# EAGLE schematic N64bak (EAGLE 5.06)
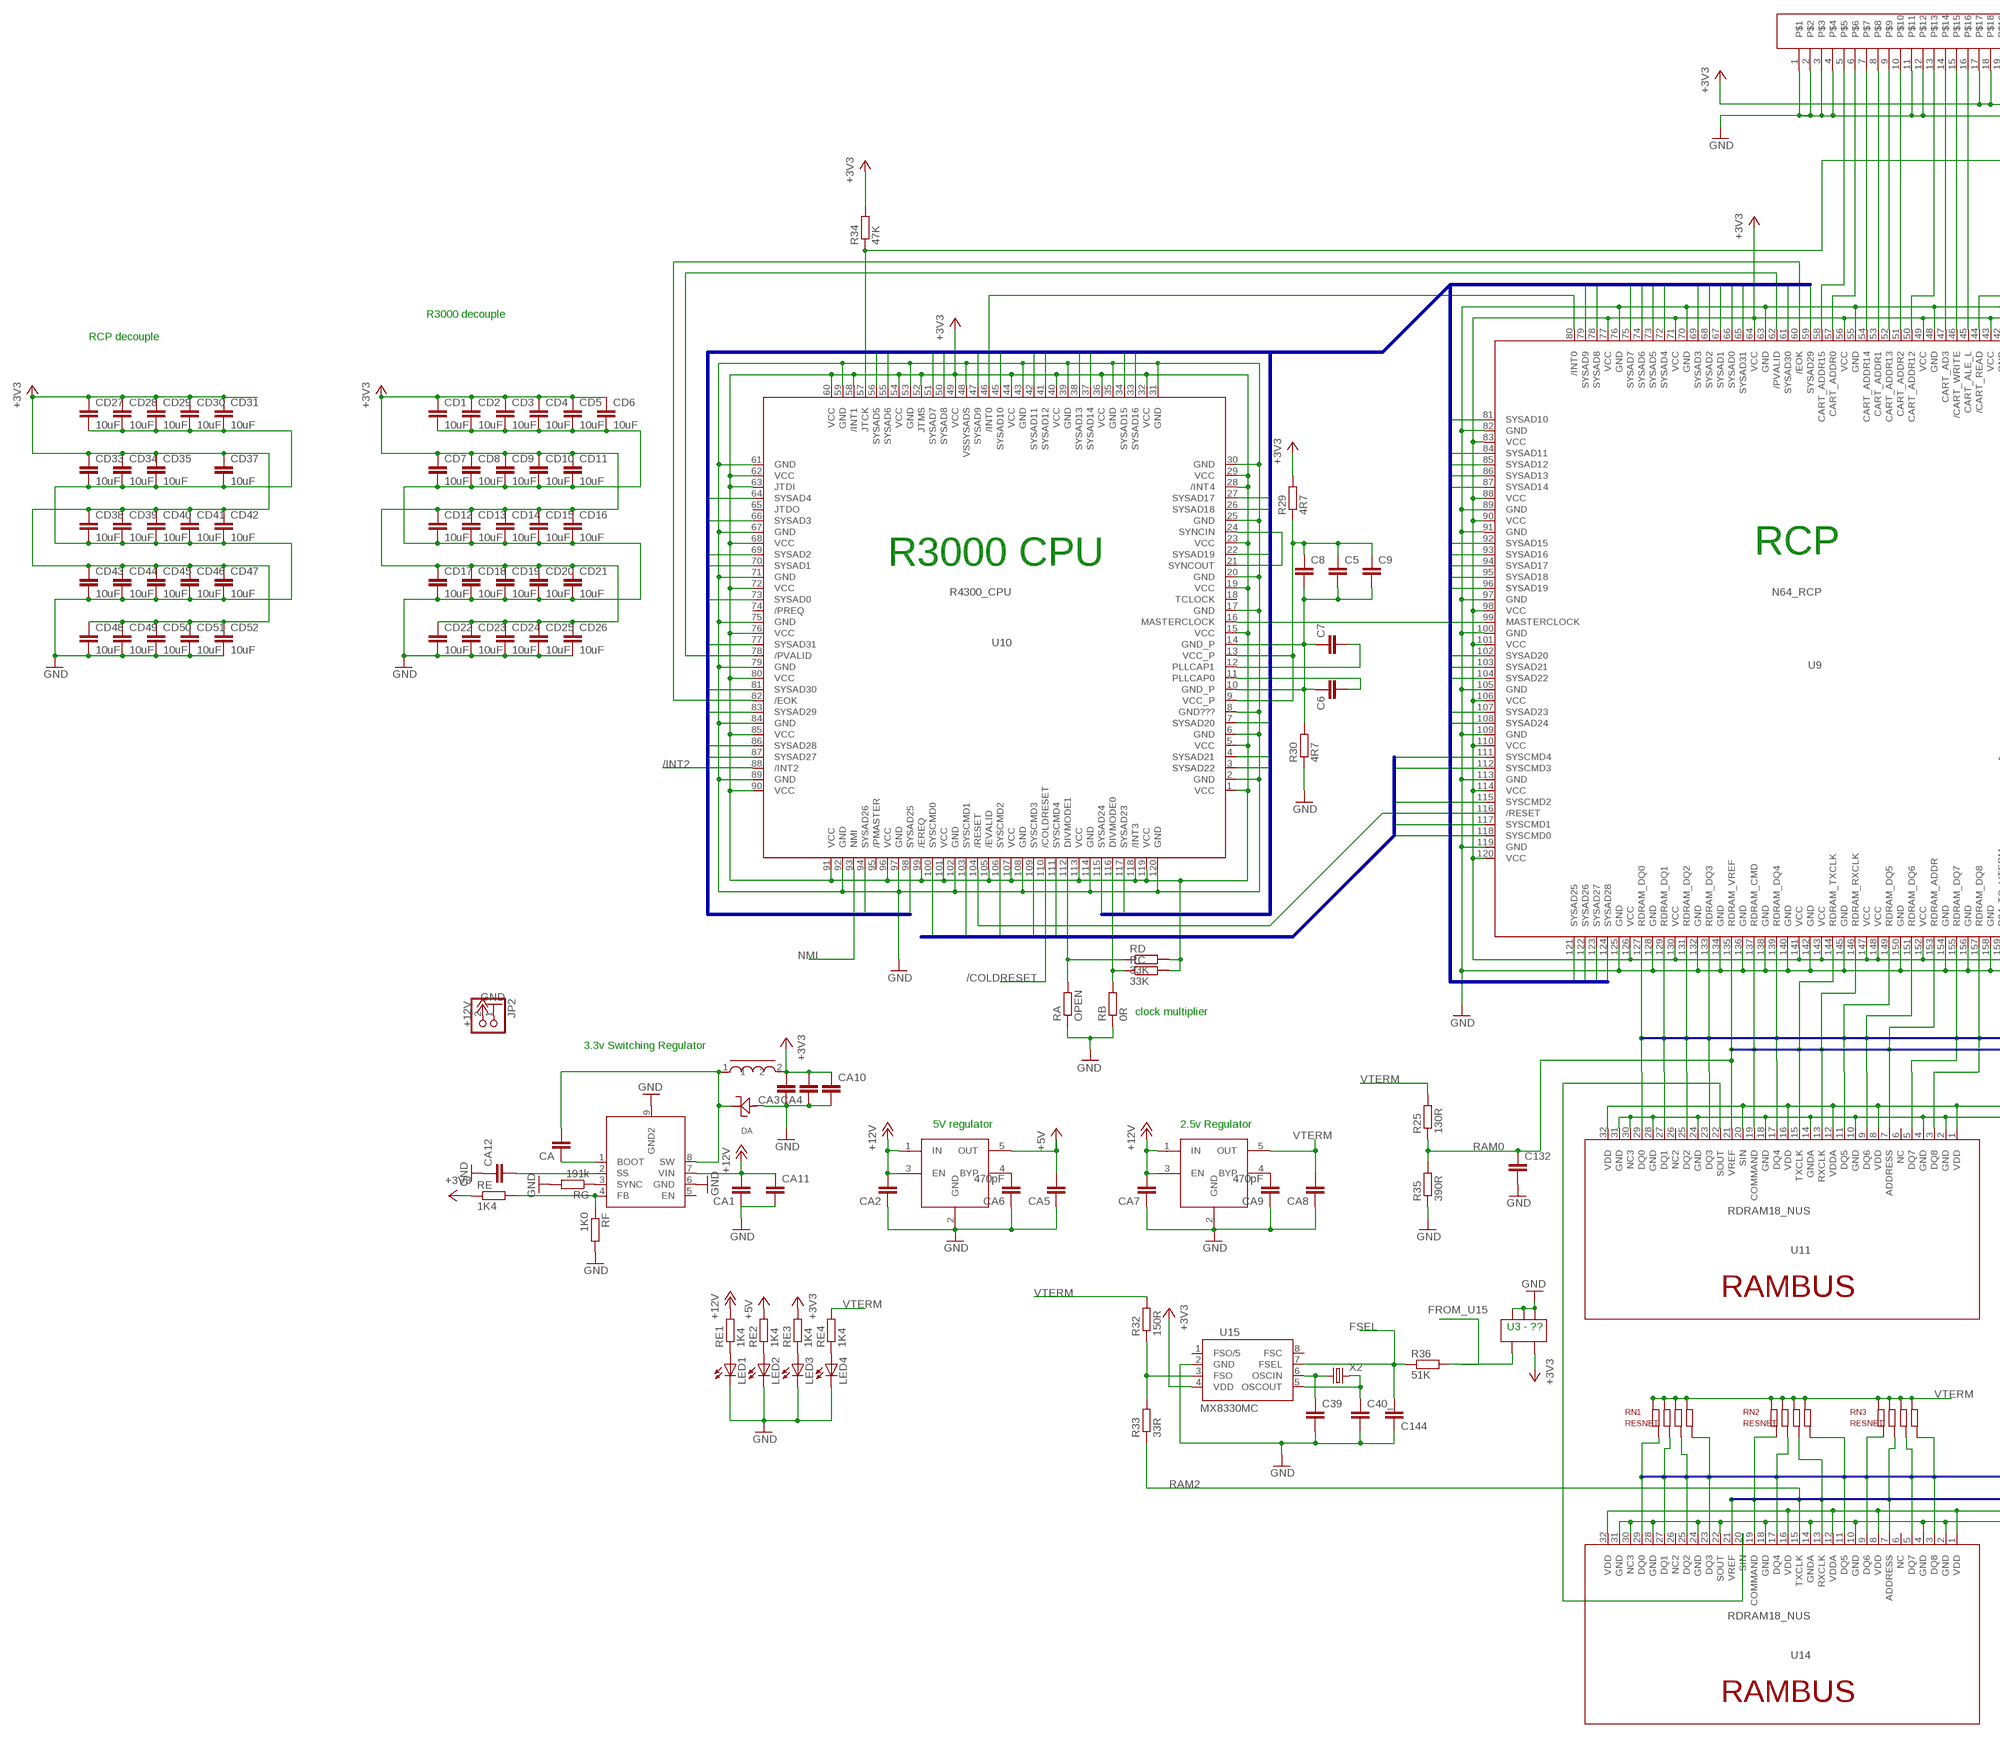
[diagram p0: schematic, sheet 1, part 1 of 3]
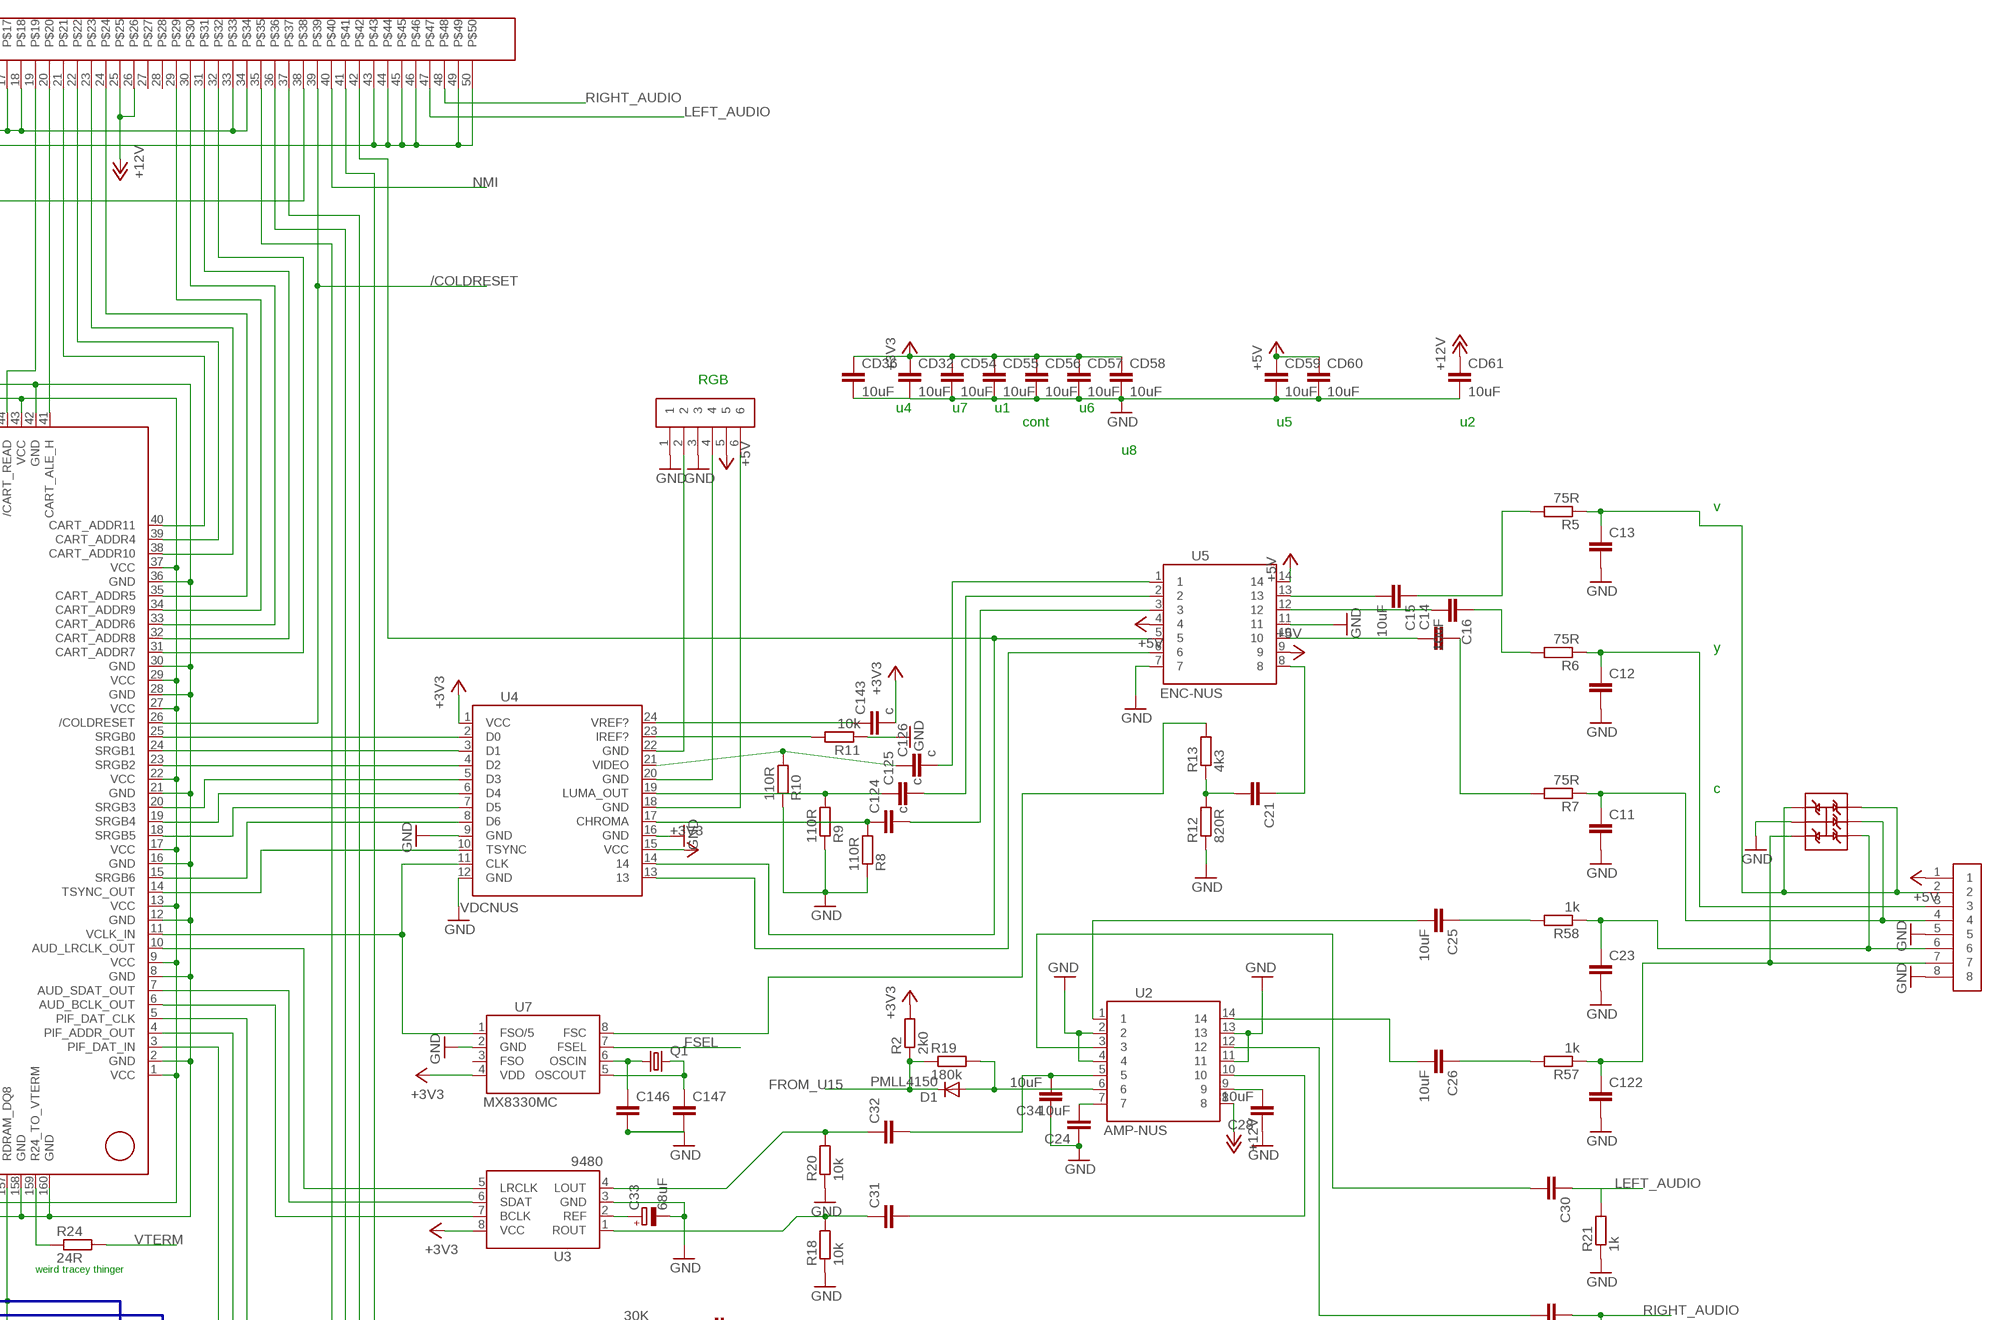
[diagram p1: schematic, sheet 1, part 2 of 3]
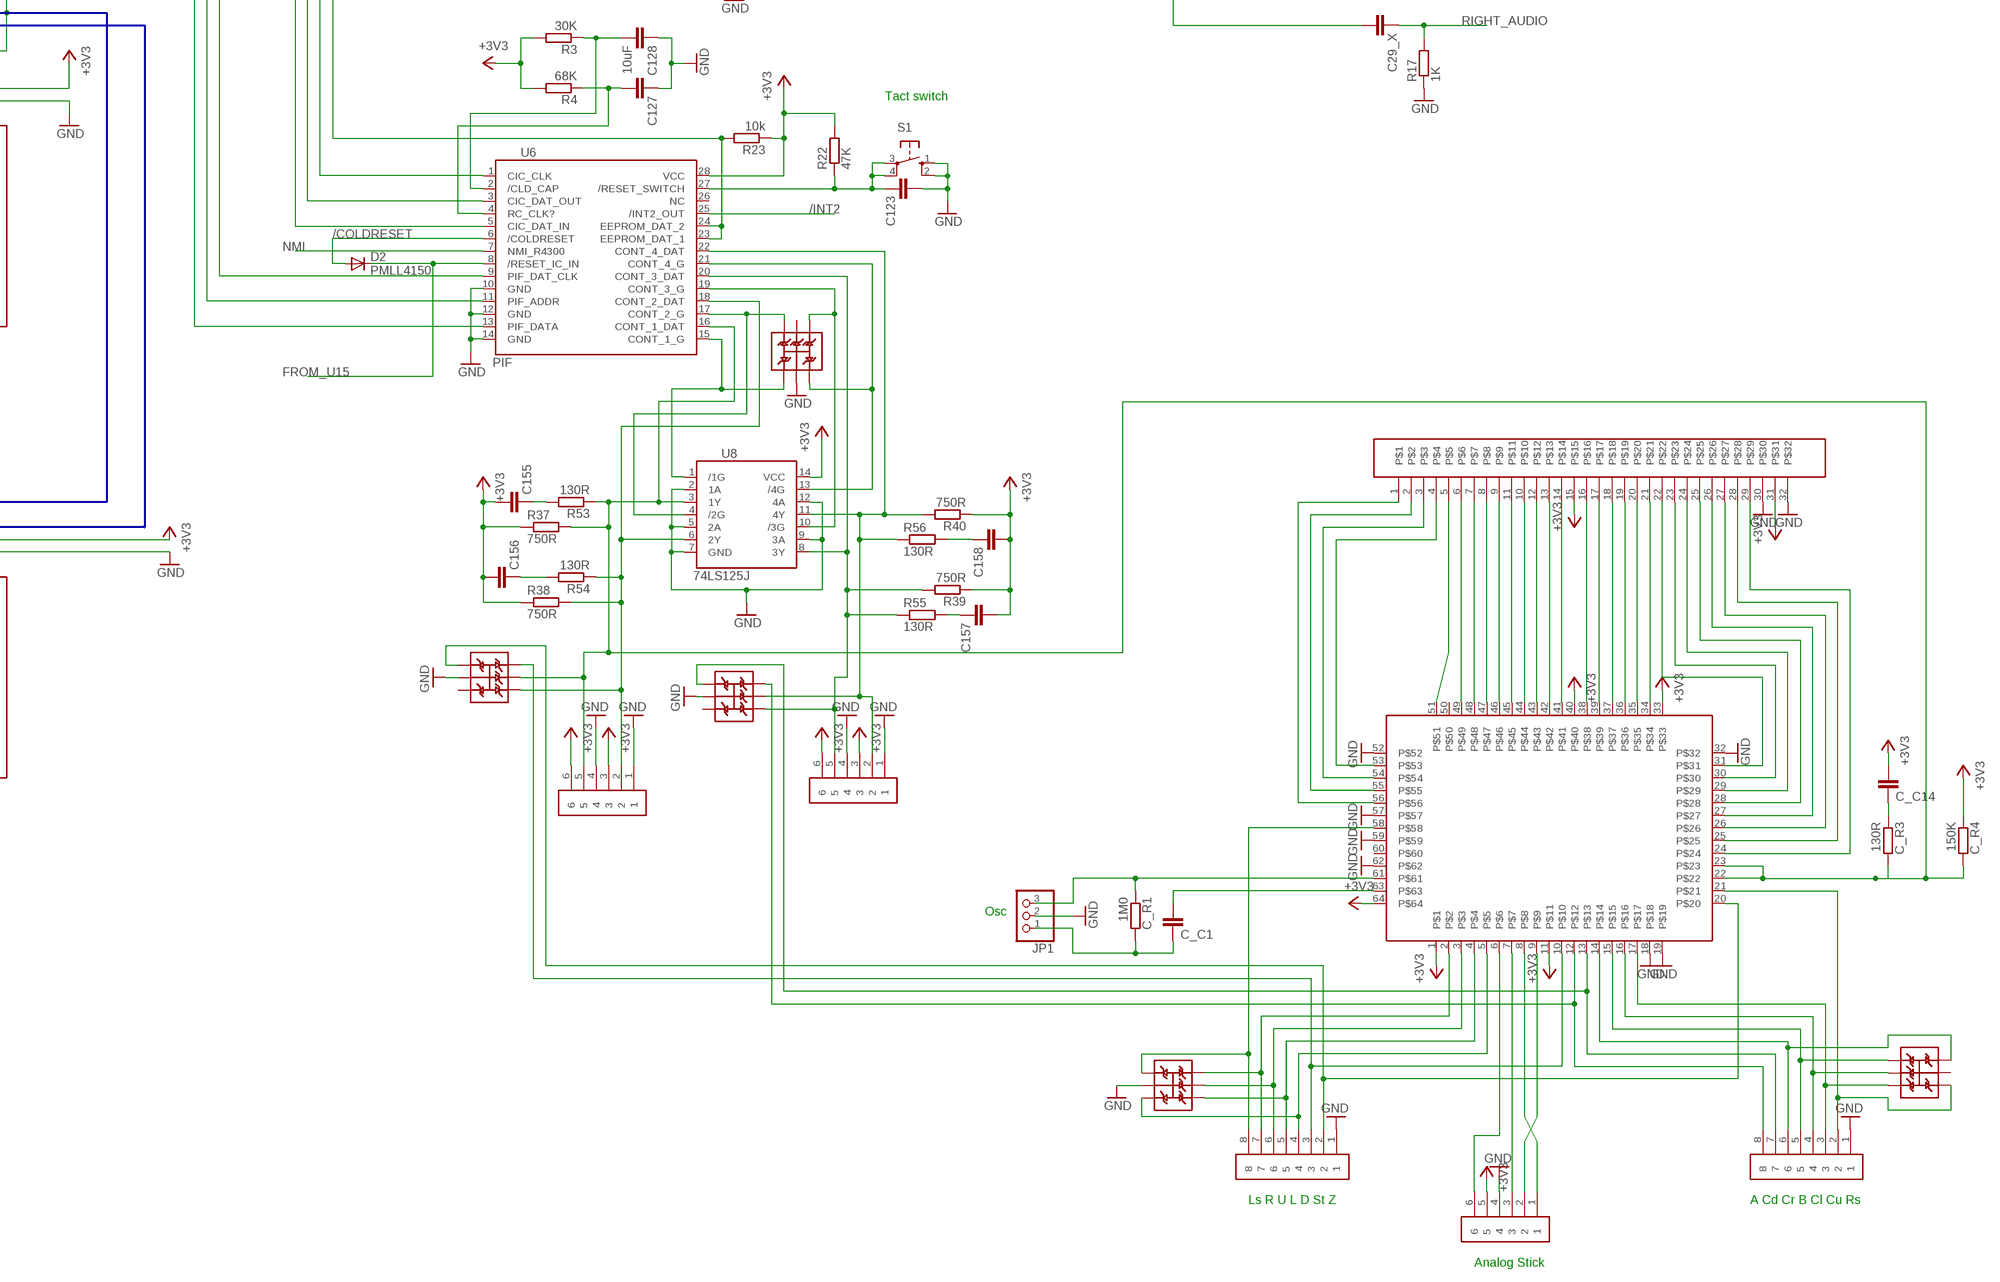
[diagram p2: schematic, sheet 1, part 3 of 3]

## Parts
3V3  LM22680  [PSOP-8]
AV  PINHEAD-1X8  [2MMPINHEAD-1X8]
BUTT1  PINHEAD-1X8  [2MMPINHEAD-1X8]
BUTT2  PINHEAD-1X8  [2MMPINHEAD-1X8]
C5  C-EUC0805K  [C0805K]
C6  C-EUC0805  [C0805]
C7  C-EUC0805  [C0805]
C8  C-EUC0805  [C0805]
C9  C-EUC0805  [C0805]
C11  C-EUC0805  [C0805]
C12  C-EUC0805  [C0805]
C13  C-EUC0805  [C0805]
C14  C-EUC0805  [C0805]
C15  10uF  C-EUC0805  [C0805]
C16  10uF  C-EUC0805  [C0805]
C21  C-EUC0805  [C0805]
C23  C-EUC0805  [C0805]
C24  10uF  C-EUC0805  [C0805]
C25  10uF  C-EUC0805  [C0805]
C26  10uF  C-EUC0805  [C0805]
C28  10uF  C-EUC0805  [C0805]
C29_X  C-EUC0805  [C0805]
C30  C-EUC0805  [C0805]
C31  C-EUC0805  [C0805]
C32  C-EUC0805  [C0805]
C33  68uF  CPOL-EUC/6032-28R  [C/6032-28R]
C34  10uF  C-EUC0805  [C0805]
C39  C-EUC0805  [C0805]
C40_  C-EUC0805  [C0805]
C122  C-EUC0805  [C0805]
C123  C-EUC0805  [C0805]
C124  c  C-EUC0805  [C0805]
C125  c  C-EUC0805  [C0805]
C126  c  C-EUC0805  [C0805]
C127  C-EUC0805  [C0805]
C128  10uF  C-EUC0805  [C0805]
C132  C-EUC0805  [C0805]
C143  c  C-EUC0805  [C0805]
C144  C-EUC0805  [C0805]
C146  C-EUC0805  [C0805]
C147  C-EUC0805  [C0805]
C155  C-EUC0805  [C0805]
C156  C-EUC0805  [C0805]
C157  C-EUC0805  [C0805]
C158  C-EUC0805  [C0805]
C_C1  C-EUC0805  [C0805]
C_C14  C-EUC0805  [C0805]
C_R1  1M0  R-EU_M0805  [M0805]
C_R3  130R  R-EU_M0805  [M0805]
C_R4  150K  R-EU_M0805  [M0805]
C_U1  CNT-NUS  [PQFP64]
CA  C-EUC1206K  [C1206K]
CA1  C-EUC1206K  [C1206K]
CA2  C-EUC0805K  [C0805K]
CA3  C-EUC1210K  [C1210K]
CA4  C-EUC1206K  [C1206K]
CA5  C-EUC0805K  [C0805K]
CA6  470pF  C-EUC0805K  [C0805K]
CA7  C-EUC0805K  [C0805K]
CA8  C-EUC0805K  [C0805K]
CA9  470pF  C-EUC0805K  [C0805K]
CA10  C-EUC0805K  [C0805K]
CA11  C-EUC0805K  [C0805K]
CA12  C-EUC0805K  [C0805K]
CD1  10uF  C-EUC0805  [C0805]
CD2  10uF  C-EUC0805  [C0805]
CD3  10uF  C-EUC0805  [C0805]
CD4  10uF  C-EUC0805  [C0805]
CD5  10uF  C-EUC0805  [C0805]
CD6  10uF  C-EUC0805  [C0805]
CD7  10uF  C-EUC0805  [C0805]
CD8  10uF  C-EUC0805  [C0805]
CD9  10uF  C-EUC0805  [C0805]
CD10  10uF  C-EUC0805  [C0805]
CD11  10uF  C-EUC0805  [C0805]
CD12  10uF  C-EUC0805  [C0805]
CD13  10uF  C-EUC0805  [C0805]
CD14  10uF  C-EUC0805  [C0805]
CD15  10uF  C-EUC0805  [C0805]
CD16  10uF  C-EUC0805  [C0805]
CD17  10uF  C-EUC0805  [C0805]
CD18  10uF  C-EUC0805  [C0805]
CD19  10uF  C-EUC0805  [C0805]
CD20  10uF  C-EUC0805  [C0805]
CD21  10uF  C-EUC0805  [C0805]
CD22  10uF  C-EUC0805  [C0805]
CD23  10uF  C-EUC0805  [C0805]
CD24  10uF  C-EUC0805  [C0805]
CD25  10uF  C-EUC0805  [C0805]
CD26  10uF  C-EUC0805  [C0805]
CD27  10uF  C-EUC0805  [C0805]
CD28  10uF  C-EUC0805  [C0805]
CD29  10uF  C-EUC0805  [C0805]
CD30  10uF  C-EUC0805  [C0805]
CD31  10uF  C-EUC0805  [C0805]
CD32  10uF  C-EUC0805  [C0805]
CD33  10uF  C-EUC0805  [C0805]
CD34  10uF  C-EUC0805  [C0805]
CD35  10uF  C-EUC0805  [C0805]
CD36  10uF  C-EUC0805  [C0805]
CD37  10uF  C-EUC0805  [C0805]
CD38  10uF  C-EUC0805  [C0805]
CD39  10uF  C-EUC0805  [C0805]
CD40  10uF  C-EUC0805  [C0805]
CD41  10uF  C-EUC0805  [C0805]
CD42  10uF  C-EUC0805  [C0805]
CD43  10uF  C-EUC0805  [C0805]
CD44  10uF  C-EUC0805  [C0805]
CD45  10uF  C-EUC0805  [C0805]
CD46  10uF  C-EUC0805  [C0805]
CD47  10uF  C-EUC0805  [C0805]
CD48  10uF  C-EUC0805  [C0805]
CD49  10uF  C-EUC0805  [C0805]
CD50  10uF  C-EUC0805  [C0805]
CD51  10uF  C-EUC0805  [C0805]
CD52  10uF  C-EUC0805  [C0805]
CD54  10uF  C-EUC0805  [C0805]
CD55  10uF  C-EUC0805  [C0805]
CD56  10uF  C-EUC0805  [C0805]
CD57  10uF  C-EUC0805  [C0805]
CD58  10uF  C-EUC0805  [C0805]
CD59  10uF  C-EUC0805  [C0805]
CD60  10uF  C-EUC0805  [C0805]
CD61  10uF  C-EUC0805  [C0805]
CONT1  PINHEAD-1X6  [2MMPINHEAD-1X6]
CONT2  PINHEAD-1X6  [2MMPINHEAD-1X6]
D1  PMLL4150  [SOD80C]
D2  PMLL4150  [SOD80C]
DA  STKYDIODE  [STKYDIODE]
JOY  PINHEAD-1X6  [2MMPINHEAD-1X6]
JP1  PINHD-1X3  [1X03]
JP2  PINHD-1X2  [1X02]
LED1  LEDCHIPLED_0805  [CHIPLED_0805]
LED2  LEDCHIPLED_0805  [CHIPLED_0805]
LED3  LEDCHIPLED_0805  [CHIPLED_0805]
LED4  LEDCHIPLED_0805  [CHIPLED_0805]
Q1  CRYTALHC49S  [HC49/S]
R2  2k0  R-EU_M0805  [M0805]
R3  30K  R-EU_M0805  [M0805]
R4  68K  R-EU_M0805  [M0805]
R5  75R  R-EU_M0805  [M0805]
R6  75R  R-EU_M0805  [M0805]
R7  75R  R-EU_M0805  [M0805]
R8  110R  R-EU_M0805  [M0805]
R9  110R  R-EU_M0805  [M0805]
R10  110R  R-EU_M0805  [M0805]
R11  10k  R-EU_M0805  [M0805]
R12  820R  R-EU_M0805  [M0805]
R13  4k3  R-EU_M0805  [M0805]
R17  1K  R-EU_M0805  [M0805]
R18  10k  R-EU_M0805  [M0805]
R19  180k  R-EU_M0805  [M0805]
R20  10k  R-EU_M0805  [M0805]
R21  1k  R-EU_M0805  [M0805]
R22  47K  R-EU_M0805  [M0805]
R23  10k  R-EU_M0805  [M0805]
R24  24R  R-EU_M0805  [M0805]
R25  130R  R-EU_M0805  [M0805]
R29  4R7  R-EU_M0805  [M0805]
R30  4R7  R-EU_M0805  [M0805]
R32  150R  R-EU_M0805  [M0805]
R33  33R  R-EU_M0805  [M0805]
R34  47K  R-EU_M0805  [M0805]
R35  390R  R-EU_M0805  [M0805]
R36  51K  R-EU_M0805  [M0805]
R37  750R  R-EU_M0805  [M0805]
R38  750R  R-EU_M0805  [M0805]
R39  750R  R-EU_M0805  [M0805]
R40  750R  R-EU_M0805  [M0805]
R53  130R  R-EU_M0805  [M0805]
R54  130R  R-EU_M0805  [M0805]
R55  130R  R-EU_M0805  [M0805]
R56  130R  R-EU_M0805  [M0805]
R57  1k  R-EU_M0805  [M0805]
R58  1k  R-EU_M0805  [M0805]
RA  OPEN  R-EU_M0805  [M0805]
RB  0R  R-EU_M0805  [M0805]
RC  33K  R-EU_M0805  [M0805]
RD  33K  R-EU_M0805  [M0805]
RE  1K4  R-EU_M0805  [M0805]
RE1  1K4  R-EU_M0805  [M0805]
RE2  1K4  R-EU_M0805  [M0805]
RE3  1K4  R-EU_M0805  [M0805]
RE4  1K4  R-EU_M0805  [M0805]
RF  1K0  R-EU_M0805  [M0805]
RG  191k  R-EU_M0805  [M0805]
RGB  PINHEAD-1X6  [2MMPINHEAD-1X6]
RN1  RESNET  [RESARRAY]
RN2  RESNET  [RESARRAY]
RN3  RESNET  [RESARRAY]
S1  10-XX  [B3F-10XX]
TVS1  TVS  [SC-74]
TVS2  TVS  [SC-74]
TVS3  TVS  [SC-74]
TVS4  TVS  [SC-74]
TVS5  TVS  [SC-74]
TVS6  TVS  [SC-74]
U2  AMP-NUS  [SO14]
U3  9480  [SO8]
U3_  U3  [SOT23-5]
U4  VDCNUS  [SO24]
U5  ENC-NUS  [SO14]
U6  PIF  [SO28W]
U7  MX8330MC  [SO08]
U8  74LS125J  [QSOP14]
U9  N64_RCP  [PQFP160]
U10  R4300_CPU  [QFP120]
U11  RDRAM18_NUS  [SHP32]
U12  MIC5219  [SOT23-5]
U13  MIC5219  [SOT23-5]
U14  RDRAM18_NUS  [SHP32]
U15  MX8330MC  [SO08]
U$37  PINHEAD-25X2  [PINHEAD-25X2]
U$38  PINHEAD-16X2SMALLER  [2MMPINHEAD-16X2]
U$52  INDUCTOR  [INDUCTOR]
X2  CRYTALHC49S  [HC49/S]

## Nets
3V3: C143.2 R2.2 R34.2 RE3.2 RE.1 ; supply symbol labelled +3V3
+3V3: C155.2 C156.2 C157.2 C158.2 C_C14.2 C_R4.1 C_U1.1 C_U1.11 C_U1.33 C_U1.40 C_U1.64 CA3.2 CA4.2 CA10.1 CD1.1 CD2.1 CD3.1 CD4.1 CD5.1 CD6.1 CD7.1 CD8.1 CD9.1 CD10.1 CD11.1 CD12.1 CD13.1 CD14.1 CD15.1 CD16.1 CD17.1 CD18.1 CD19.1 CD20.1 CD21.1 CD22.1 CD23.1 CD24.1 CD25.1 CD26.1 CD27.1 CD28.1 CD29.1 CD30.1 CD31.1 CD32.1 CD33.1 CD34.1 CD35.1 CD36.1 CD37.1 CD38.1 CD39.1 CD40.1 CD41.1 CD42.1 CD43.1 CD44.1 CD45.1 CD46.1 CD47.1 CD48.1 CD49.1 CD50.1 CD51.1 CD52.1 CD54.1 CD55.1 CD56.1 CD57.1 CD58.1 CONT1.3 CONT1.6 CONT2.3 CONT2.6 JOY.5 R3.2 R4.2 R22.2 R23.1 R29.2 R37.1 R38.1 R39.1 R40.1 RC.2 RD.2 U3.8(VCC) U3_.5 U4.1(VCC) U4.15(VCC) U6.28(VCC) U7.4(VDD) U8.14(VCC) U9.1(VCC) U9.9(VCC) U9.13(VCC) U9.17(VCC) U9.22(VCC) U9.27(VCC) U9.29(VCC) U9.37(VCC) U9.43(VCC) U9.49(VCC) U9.56(VCC) U9.64(VCC) U9.71(VCC) U9.77(VCC) U9.83(VCC) U9.88(VCC) U9.90(VCC) U9.98(VCC) U9.101(VCC) U9.106(VCC) U9.110(VCC) U9.114(VCC) U9.120(VCC) U9.126(VCC) U9.130(VCC) U9.141(VCC) U9.143(VCC) U9.147(VCC) U9.148(VCC) U9.152(VCC) U10.1(VCC) U10.5(VCC) U10.15(VCC) U10.19(VCC) U10.23(VCC) U10.28(/INT4) U10.29(VCC) U10.32(VCC) U10.36(VCC) U10.40(VCC) U10.44(VCC) U10.49(VCC) U10.52(JTMS) U10.54(VCC) U10.58(/INT1) U10.60(VCC) U10.62(VCC) U10.63(JTDI) U10.68(VCC) U10.72(VCC) U10.76(VCC) U10.80(VCC) U10.85(VCC) U10.90(VCC) U10.91(VCC) U10.96(VCC) U10.99(/EREQ) U10.101(VCC) U10.105(/EVALID) U10.107(VCC) U10.113(VCC) U10.118(/INT3) U10.119(VCC) U11.1(VDD) U11.8(VDD) U11.12(VDDA) U11.16(VDD) U11.20(SIN) U11.32(VDD) U14.1(VDD) U14.8(VDD) U14.12(VDDA) U14.16(VDD) U14.32(VDD) U15.4(VDD) U$37.17 U$37.18 U$37.33 U$37.34 U$38.15 U$38.31 U$52.2
+5V: AV.1 CA5.2 CD59.1 CD60.1 RE2.2 RGB.5 U5.4 U5.9 U5.14 U13.5(OUT)
+12V: 3V3.7(VIN) CA1.2 CA2.2 CA7.2 CA11.1 CD61.1 JP2.2 RE1.2 U2.8 U12.1(IN) U12.3(EN) U13.1(IN) U13.3(EN) U$37.25 U$37.26
/COLDRESET: D2.A U6.6(/COLDRESET) U9.26(/COLDRESET) U10.110(/COLDRESET) U$37.39
/INT2: U6.25(/INT2_OUT) U10.88(/INT2)
ADJ: 3V3.4(FB) RE.2 RF.1
C16X: C16.1 R6.2
C_C11: C_C1.1 C_R1.2 JP1.1
DQ0: RN1.1 U9.127(RDRAM_DQ0) U11.29(DQ0) U14.29(DQ0)
DQ1: RN1.2 U9.129(RDRAM_DQ1) U11.27(DQ1) U14.27(DQ1)
DQ2: RN1.3 U9.131(RDRAM_DQ2) U11.25(DQ2) U14.25(DQ2)
DQ3: RN1.4 U9.133(RDRAM_DQ3) U11.23(DQ3) U14.23(DQ3)
DQ4: RN2.2 U9.139(RDRAM_DQ4) U11.17(DQ4) U14.17(DQ4)
DQ5: RN2.4 U9.149(RDRAM_DQ5) U11.11(DQ5) U14.11(DQ5)
DQ6: RN3.1 U9.151(RDRAM_DQ6) U11.9(DQ6) U14.9(DQ6)
DQ7: RN3.3 U9.155(RDRAM_DQ7) U11.5(DQ7) U14.5(DQ7)
DQ8: RN3.4 U9.157(RDRAM_DQ8) U11.3(DQ8) U14.3(DQ8)
FROM_U15: D1.C D2.C R2.1 R19.1 R36.2 U3_.4 U6.8(/RESET_IC_IN)
FSEL: C144.2 R36.1 U7.7(FSEL) U15.7(FSEL)
FSO1: R32.1 R33.2 U15.3(FSO)
GND: 3V3.6(GND) 3V3.9(GND2) AV.5 AV.8 BUTT1.1 BUTT2.1 C11.2 C12.2 C13.2 C23.2 C24.1 C28.1 C33.- C34.1 C39.2 C40_.2 C122.2 C123.2 C127.1 C128.1 C132.2 C144.1 C146.2 C147.2 C_U1.18 C_U1.19 C_U1.32 C_U1.52 C_U1.57 C_U1.59 C_U1.62 CA1.1 CA2.1 CA3.1 CA4.1 CA5.1 CA6.1 CA7.1 CA8.1 CA9.1 CA10.2 CA11.2 CA12.1 CD1.2 CD2.2 CD3.2 CD4.2 CD5.2 CD6.2 CD7.2 CD8.2 CD9.2 CD10.2 CD11.2 CD12.2 CD13.2 CD14.2 CD15.2 CD16.2 CD17.2 CD18.2 CD19.2 CD20.2 CD21.2 CD22.2 CD23.2 CD24.2 CD25.2 CD26.2 CD27.2 CD28.2 CD29.2 CD30.2 CD31.2 CD32.2 CD33.2 CD34.2 CD35.2 CD36.2 CD37.2 CD38.2 CD39.2 CD40.2 CD41.2 CD42.2 CD43.2 CD44.2 CD45.2 CD46.2 CD47.2 CD48.2 CD49.2 CD50.2 CD51.2 CD52.2 CD54.2 CD55.2 CD56.2 CD57.2 CD58.2 CD59.2 CD60.2 CD61.2 CONT1.1 CONT1.4 CONT2.1 CONT2.4 DA.+ JOY.4 JP1.2 JP2.1 LED1.C LED2.C LED3.C LED4.C R8.1 R9.1 R10.1 R11.1 R12.1 R17.1 R18.1 R20.1 R21.1 R30.1 R35.1 RA.1 RB.1 RF.2 RG.2 RGB.1 RGB.3 S1.1(S) S1.2(S1) TVS1.2 TVS2.2 TVS3.2 TVS4.2 TVS5.2 U2.2 U2.4 U2.11 U2.13 U3.3(GND) U3_.1 U3_.2 U3_.3 U4.9(GND) U4.12(GND) U4.16(GND) U5.7 U5.11 U6.10(GND) U6.12(GND) U6.14(GND) U7.2(GND) U8.2(1A) U8.5(2A) U8.7(GND) U8.9(3A) U8.12(4A) U9.2(GND) U9.8(GND) U9.12(GND) U9.16(GND) U9.21(GND) U9.28(GND) U9.30(GND) U9.36(GND) U9.42(GND) U9.48(GND) U9.55(GND) U9.63(GND) U9.70(GND) U9.76(GND) U9.82(GND) U9.89(GND) U9.91(GND) U9.97(GND) U9.100(GND) U9.105(GND) U9.109(GND) U9.113(GND) U9.119(GND) U9.125(GND) U9.128(GND) U9.132(GND) U9.134(GND) U9.136(GND) U9.138(GND) U9.140(GND) U9.142(GND) U9.145(GND) U9.150(GND) U9.154(GND) U9.156(GND) U9.158(GND) U9.160(GND) U10.2(GND) U10.6(GND) U10.8(GND???) U10.17(GND) U10.20(GND) U10.25(GND) U10.30(GND) U10.31(GND) U10.35(GND) U10.39(GND) U10.43(GND) U10.48(VSSYSADS) U10.53(GND) U10.59(GND) U10.61(GND) U10.67(GND) U10.71(GND) U10.75(GND) U10.79(GND) U10.84(GND) U10.89(GND) U10.92(GND) U10.97(GND) U10.102(GND) U10.108(GND) U10.114(GND) U10.120(GND) U11.2(GND) U11.4(GND) U11.10(GND) U11.14(GNDA) U11.18(GND) U11.24(GND) U11.28(GND) U11.30(NC3) U11.31(GND) U12.2(GND) U13.2(GND) U14.2(GND) U14.4(GND) U14.10(GND) U14.14(GNDA) U14.18(GND) U14.22(SOUT) U14.24(GND) U14.28(GND) U14.30(NC3) U14.31(GND) U15.2(GND) U$37.1 U$37.2 U$37.3 U$37.4 U$37.11 U$37.12 U$37.43 U$37.44 U$37.45 U$37.46 U$37.49 U$37.50 U$38.30 U$38.32
INT0: U9.80(/INT0) U10.46(/INT0)
LEFT_AUDIO: C30.1 R21.2 U$37.47
N$1: C156.1 R54.2
N$2: C155.1 R53.2
N$3: U4.11(CLK) U7.1(FSO/5) U9.11(VCLK_IN)
N$4: R24.1 U9.159(R24_TO_VTERM)
N$5: C147.1 Q1.2 U7.5(OSCOUT)
N$6: C146.1 Q1.1 U7.6(OSCIN)
N$7: BUTT1.2 C_U1.20 TVS3.1
N$8: RGB.2 U4.22(GND)
N$9: RGB.4 U4.20(GND)
N$10: U6.9(PIF_DAT_CLK) U9.5(PIF_DAT_CLK)
N$11: U6.11(PIF_ADDR) U9.4(PIF_ADDR_OUT)
N$12: U6.13(PIF_DATA) U9.3(PIF_DAT_IN)
N$13: TVS2.1 U6.15(CONT_1_G) U8.1(/1G)
N$14: C_R3.2 C_R4.2 C_U1.22 C_U1.23 CONT1.5 R37.2 R53.1 TVS3.5 U6.16(CONT_1_DAT) U8.3(1Y)
N$15: BUTT1.3 C_U1.10 TVS3.6
N$16: LED1.A RE1.1
N$17: CONT1.2 R38.2 R54.1 TVS3.4 U6.18(CONT_2_DAT) U8.6(2Y)
N$18: TVS2.4 U6.19(CONT_3_G) U8.10(/3G)
N$19: CONT2.5 R39.2 R55.1 TVS4.4 U6.20(CONT_3_DAT) U8.8(3Y)
N$20: TVS2.3 U6.21(CONT_4_G) U8.13(/4G)
N$21: CONT2.2 R40.2 R56.1 TVS4.5 U6.22(CONT_4_DAT) U8.11(4Y)
N$22: U4.2(D0) U9.25(SRGB0)
N$23: U9.116(/RESET) U10.104(/RESET)
N$24: TVS2.6 U6.17(CONT_2_G) U8.4(/2G)
N$25: U9.62(/PVALID) U10.78(/PVALID)
N$26: U9.60(/EOK) U10.82(/EOK)
N$27: C123.1 R22.1 S1.3(P) S1.4(P1) U6.27(/RESET_SWITCH)
N$28: U4.3(D1) U9.24(SRGB1)
N$29: RB.2 RC.1 U10.116(DIVMODE0)
N$31: U9.39(CART_ADDR4) U$37.22
N$32: RA.2 RD.1 U10.112(DIVMODE1)
N$33: U9.58(CART_ADDR15) U$37.5
N$34: U9.57(CART_ADDR0) U$37.6
N$35: U9.54(CART_ADDR14) U$37.7
N$36: U9.53(CART_ADDR1) U$37.8
N$37: U9.52(CART_ADDR13) U$37.9
N$38: U9.51(CART_ADDR2) U$37.10
N$39: U9.99(MASTERCLOCK) U10.16(MASTERCLOCK)
N$40: U9.50(CART_ADDR12) U$37.13
N$41: U9.47(CART_AD3) U$37.14
N$42: U9.46(/CART_WRITE) U$37.15
N$43: U9.45(CART_ALE_L) U$37.16
N$44: U9.44(/CART_READ) U$37.19
N$45: U9.41(CART_ALE_H) U$37.20
N$46: U9.38(CART_ADDR10) U$37.23
N$47: U9.35(CART_ADDR5) U$37.24
N$48: U9.34(CART_ADDR9) U$37.29
N$49: U9.33(CART_ADDR6) U$37.30
N$50: U9.32(CART_ADDR8) U$37.31
N$51: U9.31(CART_ADDR7) U$37.32
N$52: C157.1 R55.2
N$53: U6.5(CIC_DAT_IN) U$37.35
N$54: U6.3(CIC_DAT_OUT) U$37.36
N$55: U6.1(CIC_CLK) U$37.37
N$56: R23.2 U6.23(EEPROM_DAT_1) U6.24(EEPROM_DAT_2) U$37.41
N$57: C5.1 C8.1 C9.1 R29.1 U10.9(VCC_P) U10.13(VCC_P)
N$58: C5.2 C6.1 C7.1 C8.2 C9.2 R30.2 U10.10(GND_P) U10.14(GND_P)
N$59: C6.2 U10.11(PLLCAP0)
N$60: C7.2 U10.12(PLLCAP1)
N$61: U10.21(SYNCOUT) U10.24(SYNCIN)
N$62: U3.5(LRCLK) U9.10(AUD_LRCLK_OUT)
N$63: U3.6(SDAT) U9.7(AUD_SDAT_OUT)
N$64: U3.7(BCLK) U9.6(AUD_BCLK_OUT)
N$65: C33.+ U3.2(REF)
N$66: C127.2 R4.1 U6.4(RC_CLK?)
N$67: C128.2 R3.1 U6.2(/CLD_CAP)
N$68: U4.4(D2) U9.23(SRGB2)
N$69: U4.5(D3) U9.20(SRGB3)
N$70: U4.6(D4) U9.19(SRGB4)
N$71: U4.7(D5) U9.18(SRGB5)
N$72: U4.8(D6) U9.15(SRGB6)
N$73: U4.10(TSYNC) U9.14(TSYNC_OUT)
N$74: R11.2 U4.23(IREF?)
N$75: C126.1 R10.2 U4.21(VIDEO)
N$76: R34.1 U10.57(JTCK) U$37.38
N$77: C32.1 R20.2 U3.4(LOUT)
N$78: C31.1 R18.2 U3.1(ROUT)
N$79: C143.1 U4.24(VREF?)
N$80: C125.1 R9.2 U4.19(LUMA_OUT)
N$81: C124.1 R8.2 U4.17(CHROMA)
N$82: C158.1 R56.2
N$83: C32.2 C34.2 U2.5
N$84: C31.2 U2.10
N$85: C24.2 U2.7
N$86: C28.2 U2.9
N$87: C29_X.2 U2.12
N$88: C30.2 U2.3
N$89: D1.A R19.2 U2.6
N$90: C25.1 R58.2
N$91: C14.1 U5.10
N$93: C26.2 U2.14
N$94: AV.7 C122.1 R57.1 TVS1.3
N$95: C26.1 R57.2
N$96: C_U1.56 U$38.1
N$97: CA6.2 U13.4(BYP)
N$98: C_U1.55 U$38.2
N$99: U4.13 U5.6
N$100: U4.14 U5.5 U$37.42
N$101: C124.2 U5.3
N$102: C125.2 U5.2
N$103: C126.2 U5.1
N$104: C15.1 R5.2
N$105: C15.2 U5.13
N$106: C16.2 U5.12
N$107: AV.4 C11.1 R7.1 TVS1.5
N$108: AV.3 C12.1 R6.1
N$109: C14.2 R7.2
N$110: C21.1 U5.8
N$112: R13.2 U7.8(FSC)
N$113: C21.2 R12.2 R13.1
N$114: AV.2 C13.1 R5.1 TVS1.1 TVS1.6
N$115: RGB.6 U4.18(GND)
N$116: C_U1.8 JOY.1
N$117: C_U1.54 U$38.3
N$118: C_U1.53 U$38.4
N$119: C_U1.9 JOY.2
N$120: C_U1.51 U$38.5
N$121: C_U1.49 U$38.6
N$122: C_U1.48 U$38.7
N$123: C_U1.47 U$38.8
N$124: U9.40(CART_ADDR11) U$37.21
N$125: C_U1.46 U$38.9
N$126: C_U1.45 U$38.11
N$127: C_U1.44 U$38.10
N$128: C_U1.43 U$38.12
N$129: C_U1.42 U$38.13
N$130: C_U1.41 U$38.14
N$131: BUTT2.2 C_U1.21 TVS6.1
N$132: C_U1.38 U$38.16
N$133: C_U1.37 U$38.18
N$134: C_U1.39 U$38.17
N$135: C_U1.36 U$38.19
N$136: C_U1.35 U$38.20
N$137: C_U1.34 U$38.21
N$138: C_U1.31 U$38.22
N$139: C_U1.30 U$38.23
N$140: C_U1.29 U$38.24
N$141: C_U1.28 U$38.25
N$142: C_U1.27 U$38.26
N$143: C_U1.26 U$38.27
N$144: C_U1.25 U$38.28
N$145: C_U1.24 U$38.29
N$146: C_C14.1 C_R3.1
N$147: 3V3.2(SS) CA12.2
N$148: BUTT2.3 C_U1.17 TVS6.6
N$149: BUTT2.4 C_U1.16 TVS6.5
N$150: BUTT2.5 C_U1.15 TVS6.4
N$151: BUTT2.6 C_U1.14 TVS6.3
N$152: BUTT2.7 C_U1.13 TVS4.1
N$153: BUTT2.8 C_U1.12 TVS4.6
N$157: C_U1.7 JOY.3
N$158: C_U1.6 JOY.6
N$159: BUTT1.4 C_U1.5 TVS5.3
N$160: BUTT1.5 C_U1.4 TVS5.4
N$161: BUTT1.6 C_U1.3 TVS5.5
N$162: BUTT1.7 C_U1.2 TVS5.6
N$163: BUTT1.8 C_U1.58 TVS5.1
N$164: C_R1.1 C_U1.61 JP1.3
N$165: C_C1.2 C_U1.63
N$166: CA9.2 U12.4(BYP)
N$168: 3V3.3(SYNC) RG.1
N$170: 3V3.1(BOOT) CA.1
N$172: LED2.A RE2.1
N$173: LED4.A RE4.1
N$174: LED3.A RE3.1
NMI: U6.7(NMI_R4300) U10.93(NMI) U$37.40
OSCIN1: C39.1 U15.6(OSCIN) X2.1
OSCOUT1: C40_.1 U15.5(OSCOUT) X2.2
R58: AV.6 C23.1 R58.1 TVS1.4
RAM0: C132.1 R25.1 R35.2 U9.135(RDRAM_VREF) U11.21(VREF) U14.21(VREF)
RAM1: RN2.1 U9.137(RDRAM_CMD) U11.19(COMMAND) U14.19(COMMAND)
RAM2: R33.1 U9.144(RDRAM_TXCLK) U11.15(TXCLK) U14.15(TXCLK)
RAM3: RN2.3 U9.146(RDRAM_RXCLK) U11.13(RXCLK) U14.13(RXCLK)
RAM4: RN3.2 U9.153(RDRAM_ADDR) U11.7(ADDRESS) U14.7(ADDRESS)
RIGHT_AUDIO: C29_X.1 R17.2 U$37.48
SW: 3V3.8(SW) CA.2 DA.- U$52.1
SYSAD0: U9.66(SYSAD0) U10.73(SYSAD0)
SYSAD1: U9.67(SYSAD1) U10.70(SYSAD1)
SYSAD2: U9.68(SYSAD2) U10.69(SYSAD2)
SYSAD3: U9.69(SYSAD3) U10.66(SYSAD3)
SYSAD4: U9.72(SYSAD4) U10.64(SYSAD4)
SYSAD5: U9.73(SYSAD5) U10.56(SYSAD5)
SYSAD6: U9.74(SYSAD6) U10.55(SYSAD6)
SYSAD7: U9.75(SYSAD7) U10.51(SYSAD7)
SYSAD8: U9.78(SYSAD8) U10.50(SYSAD8)
SYSAD9: U9.79(SYSAD9) U10.47(SYSAD9)
SYSAD10: U9.81(SYSAD10) U10.45(SYSAD10)
SYSAD11: U9.84(SYSAD11) U10.42(SYSAD11)
SYSAD12: U9.85(SYSAD12) U10.41(SYSAD12)
SYSAD13: U9.86(SYSAD13) U10.38(SYSAD13)
SYSAD14: U9.87(SYSAD14) U10.37(SYSAD14)
SYSAD15: U9.92(SYSAD15) U10.34(SYSAD15)
SYSAD16: U9.93(SYSAD16) U10.33(SYSAD16)
SYSAD17: U9.94(SYSAD17) U10.27(SYSAD17)
SYSAD18: U9.95(SYSAD18) U10.26(SYSAD18)
SYSAD19: U9.96(SYSAD19) U10.22(SYSAD19)
SYSAD20: U9.102(SYSAD20) U10.7(SYSAD20)
SYSAD21: U9.103(SYSAD21) U10.4(SYSAD21)
SYSAD22: U9.104(SYSAD22) U10.3(SYSAD22)
SYSAD23: U9.107(SYSAD23) U10.117(SYSAD23)
SYSAD24: U9.108(SYSAD24) U10.115(SYSAD24)
SYSAD25: U9.121(SYSAD25) U10.98(SYSAD25)
SYSAD26: U9.122(SYSAD26) U10.94(SYSAD26)
SYSAD27: U9.123(SYSAD27) U10.87(SYSAD27)
SYSAD28: U9.124(SYSAD28) U10.86(SYSAD28)
SYSAD29: U9.59(SYSAD29) U10.83(SYSAD29)
SYSAD30: U9.61(SYSAD30) U10.81(SYSAD30)
SYSAD31: U9.65(SYSAD31) U10.77(SYSAD31)
SYSCMD0: U9.118(SYSCMD0) U10.100(SYSCMD0)
SYSCMD1: U9.117(SYSCMD1) U10.103(SYSCMD1)
SYSCMD2: U9.115(SYSCMD2) U10.106(SYSCMD2)
SYSCMD3: U9.112(SYSCMD3) U10.109(SYSCMD3)
SYSCMD4: U9.111(SYSCMD4) U10.111(SYSCMD4)
U2: C25.2 U2.1
U3: U11.22(SOUT) U14.20(SIN)
VTERM: CA8.2 R24.2 R25.2 R32.2 RE4.2 RN1.5 RN1.6 RN1.7 RN1.8 RN2.5 RN2.6 RN2.7 RN2.8 RN3.5 RN3.6 RN3.7 RN3.8 U12.5(OUT)
Unconnected: 3V3.5(EN) C_U1.50 C_U1.60 TVS2.5 TVS3.3 TVS4.3 TVS6.2 U6.26(NC) U7.3(FSO) U10.18(TCLOCK) U10.65(JTDO) U10.74(/PREQ) U10.95(/PMASTER) U11.6(NC) U11.26(NC2) U14.6(NC) U14.26(NC2) U15.1(FSO/5) U15.8(FSC) U$37.27 U$37.28

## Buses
SYSAD[0..31]
SYSCMD[0..4]
DQ[0..8]
RAM[0..6]

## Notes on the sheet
- RGB
- R3000 decouple
- u4 | u7 | u1 | u6
- RCP decouple | cont | u5 | u2
- u8
- v
- y
- R3000 CPU | RCP
- c
- clock multiplier | weird tracey thinger
- 3.3v Switching Regulator
- Tact switch
- 5V regulator | 2.5v Regulator
- U3 - ??
- Osc
- Ls R U L D St Z | A Cd Cr B Cl Cu Rs
- Analog Stick

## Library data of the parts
3V3 = Nintendo-64:LM22680
AV BUTT1 BUTT2 = Nintendo-64:PINHEAD-1X8
C5-C9 C11-C16 C21 C23-C26 C28 C29_X C30-C32 C34 C39 C40_ C122-C128 C132 C143 C144 C146 C147 C155-C158 C_C1 C_C14 CA CA1-CA12 CD1-CD52 CD54-CD61 = rcl:C-EU: CAPACITOR, European symbol
C33 = rcl:CPOL-EU: POLARIZED CAPACITOR, European symbol
C_R1 C_R3 C_R4 R2-R13 R17-R25 R29 R30 R32-R40 R53-R58 RA RB RC RD RE RE1-RE4 RF RG = rcl:R-EU_: RESISTOR, European symbol
C_U1 = Nintendo-64:CNT-NUS
CONT1 CONT2 JOY RGB = Nintendo-64:PINHEAD-1X6
D1 D2 = diode:PMLL4150: DIODE
DA = Nintendo-64:STKYDIODE
JP1 = pinhead:PINHD-1X3: PIN HEADER
JP2 = pinhead:PINHD-1X2: PIN HEADER
LED1-LED4 = led:LED: LED
Q1 X2 = crystal:CRYTAL: CRYSTAL
RN1-RN3 = Nintendo-64:RESNET
S1 = switch-omron:10-XX: OMRON SWITCH
TVS1-TVS6 = Nintendo-64:TVS
U2 = Nintendo-64:AMP-NUS
U3 = Nintendo-64:9480
U3_ = Nintendo-64:U3
U4 = Nintendo-64:VDCNUS
U5 = Nintendo-64:ENC-NUS
U6 = Nintendo-64:PIF
U7 U15 = Nintendo-64:MX8330
U8 = Nintendo-64:74LS125
U9 = Nintendo-64:N64_RCP
U10 = Nintendo-64:R4300_CPU
U11 U14 = Nintendo-64:RDRAM18_NUS
U12 U13 = Nintendo-64:MIC5219
U$37 = Nintendo-64:PINHEAD-25X2
U$38 = Nintendo-64:PINHEAD-16X2
U$52 = Nintendo-64:INDUCTOR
